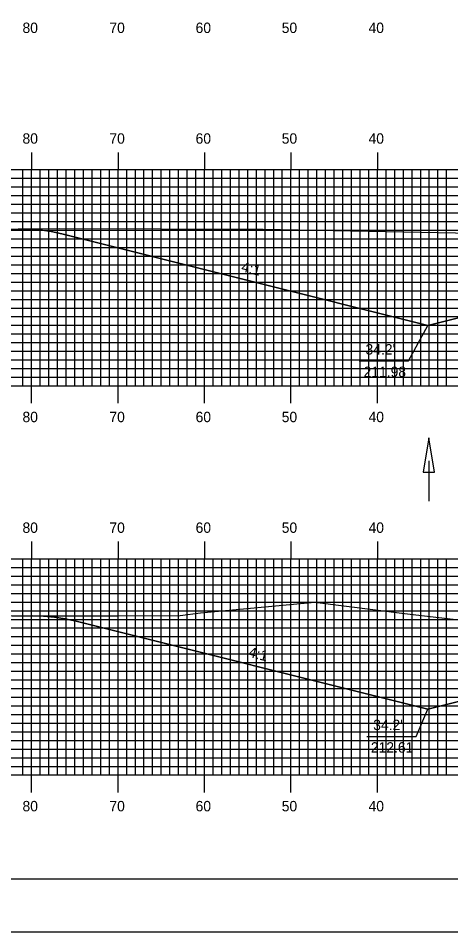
# Model space of a CAD drawing. Extents: x 1820818 to 1821161, y 442591 to 442811.
# Drawn here: x 1820902.2 to 1820952.2, y 442590.5 to 442696.2 of the extents above; entities that cross this region are included whole.
import ezdxf

# ---------------------------------------------------------------- set-up
doc = ezdxf.new("R2010")
doc.units = 0
for name, color, linetype in [('ANNOTATION', 7, 'Continuous'), ('BORDER', 7, 'Continuous'), ('D_Drainage_Ditch_Line', 7, 'Continuous'), ('D_Roadway_Centerline', 7, 'Continuous'), ('D_Roadway_SlopeLines', 7, 'Continuous'), ('H_V ANNOTATION', 7, 'Continuous'), ('MAJOR', 7, 'Continuous'), ('MINOR', 7, 'Continuous'), ('PLOT BOUNDARY', 7, 'Continuous'), ('S_Roadway_Centerline', 7, 'Continuous')]:
    doc.layers.add(name, color=color, linetype=linetype)

msp = doc.modelspace()

# ---------------------------------------------------------------- linework, layer by layer
at = {"layer": 'ANNOTATION'}
for points in [[(1820941.61, 442656.56), (1820947.3, 442656.56), (1820949.54, 442660.65)], [(1820942.5, 442613.13), (1820948.19, 442613.13), (1820949.54, 442616.27)]]:
    msp.add_lwpolyline(points, dxfattribs=at)
at = {"layer": 'BORDER'}
msp.add_lwpolyline([(1820834.12, 442596.67), (1821154.12, 442596.67), (1821154.12, 442806.67), (1820834.12, 442806.67)], close=True, dxfattribs=at)
at = {"layer": 'D_Drainage_Ditch_Line'}
msp.add_line((1820949.66, 442645.01), (1820949.66, 442640.32), dxfattribs=at)
msp.add_lwpolyline([(1820949.01, 442643.7), (1820950.32, 442643.7), (1820949.66, 442647.64)], close=True, dxfattribs=at)
at = {"layer": 'D_Roadway_Centerline'}
for points in [[(1820902.22, 442671.82), (1820903.47, 442671.8), (1820904.72, 442671.69), (1820905.97, 442671.5), (1820907.22, 442671.23), (1820949.54, 442660.65), (1820953.54, 442661.65), (1820963.72, 442664.19), (1820971.72, 442664.51), (1820983.72, 442664.75), (1820995.72, 442664.51), (1821005.72, 442664.11), (1821015.72, 442661.61), (1821019.72, 442660.61), (1821053.37, 442669.03), (1821054.62, 442669.3), (1821055.87, 442669.51), (1821057.12, 442669.64), (1821058.37, 442669.7)], [(1820903.86, 442627.07), (1820905.11, 442627.03), (1820906.36, 442626.91), (1820907.61, 442626.72), (1820908.86, 442626.44), (1820949.54, 442616.27), (1820953.54, 442617.27), (1820963.72, 442619.82), (1820971.72, 442620.14), (1820983.72, 442620.38), (1820995.72, 442620.14), (1821005.72, 442619.74), (1821015.72, 442617.24), (1821019.72, 442616.24), (1821053.46, 442624.67), (1821054.71, 442624.94), (1821055.96, 442625.13), (1821057.21, 442625.24), (1821058.46, 442625.26)]]:
    msp.add_lwpolyline(points, dxfattribs=at)
at = {"layer": 'D_Roadway_SlopeLines'}
for points in [[(1820949.54, 442660.65), (1820907.22, 442671.23), (1820905.97, 442671.5), (1820904.72, 442671.69), (1820903.47, 442671.8), (1820902.22, 442671.82)], [(1820963.72, 442664.19), (1820949.54, 442660.65)], [(1820949.54, 442616.27), (1820908.86, 442626.44), (1820907.61, 442626.72), (1820906.36, 442626.91), (1820905.11, 442627.03), (1820903.86, 442627.07)], [(1820963.72, 442619.82), (1820949.54, 442616.27)]]:
    msp.add_lwpolyline(points, dxfattribs=at)
at = {"layer": 'MAJOR'}
for p, q in [((1820903.72, 442680.67), (1820903.72, 442678.67)), ((1820913.72, 442680.67), (1820913.72, 442678.67)), ((1820923.72, 442680.67), (1820923.72, 442678.67)), ((1820933.72, 442680.67), (1820933.72, 442678.67)), ((1820943.72, 442680.67), (1820943.72, 442678.67)), ((1820843.72, 442678.67), (1821123.72, 442678.67)), ((1820843.72, 442678.67), (1821123.72, 442678.67)), ((1820903.72, 442653.67), (1820903.72, 442678.67)), ((1820913.72, 442653.67), (1820913.72, 442678.67)), ((1820923.72, 442653.67), (1820923.72, 442678.67)), ((1820933.72, 442653.67), (1820933.72, 442678.67)), ((1820943.72, 442653.67), (1820943.72, 442678.67)), ((1820843.72, 442673.67), (1821123.72, 442673.67)), ((1820843.72, 442668.67), (1821123.72, 442668.67)), ((1820843.72, 442663.67), (1821123.72, 442663.67)), ((1820843.72, 442658.67), (1821123.72, 442658.67)), ((1820843.72, 442653.67), (1821123.72, 442653.67)), ((1820843.72, 442653.67), (1821123.72, 442653.67)), ((1820903.72, 442651.66), (1820903.72, 442653.67)), ((1820913.72, 442651.66), (1820913.72, 442653.67)), ((1820923.72, 442651.66), (1820923.72, 442653.67)), ((1820933.72, 442651.66), (1820933.72, 442653.67)), ((1820943.72, 442651.66), (1820943.72, 442653.67)), ((1820903.72, 442635.67), (1820903.72, 442633.67)), ((1820913.72, 442635.67), (1820913.72, 442633.67)), ((1820923.72, 442635.67), (1820923.72, 442633.67)), ((1820933.72, 442635.67), (1820933.72, 442633.67)), ((1820943.72, 442635.67), (1820943.72, 442633.67)), ((1820843.72, 442633.67), (1821123.72, 442633.67)), ((1820843.72, 442633.67), (1821123.72, 442633.67)), ((1820903.72, 442608.67), (1820903.72, 442633.67)), ((1820913.72, 442608.67), (1820913.72, 442633.67)), ((1820923.72, 442608.67), (1820923.72, 442633.67)), ((1820933.72, 442608.67), (1820933.72, 442633.67)), ((1820943.72, 442608.67), (1820943.72, 442633.67)), ((1820843.72, 442628.67), (1821123.72, 442628.67)), ((1820843.72, 442623.67), (1821123.72, 442623.67)), ((1820843.72, 442618.67), (1821123.72, 442618.67)), ((1820843.72, 442613.67), (1821123.72, 442613.67)), ((1820843.72, 442608.67), (1821123.72, 442608.67)), ((1820843.72, 442608.67), (1821123.72, 442608.67)), ((1820903.72, 442606.66), (1820903.72, 442608.67)), ((1820913.72, 442606.66), (1820913.72, 442608.67)), ((1820923.72, 442606.66), (1820923.72, 442608.67)), ((1820933.72, 442606.66), (1820933.72, 442608.67)), ((1820943.72, 442606.66), (1820943.72, 442608.67))]:
    msp.add_line(p, q, dxfattribs=at)
at = {"layer": 'MINOR'}
for p, q in [((1820902.72, 442653.67), (1820902.72, 442678.67)), ((1820904.72, 442653.67), (1820904.72, 442678.67)), ((1820905.72, 442653.67), (1820905.72, 442678.67)), ((1820906.72, 442653.67), (1820906.72, 442678.67)), ((1820907.72, 442653.67), (1820907.72, 442678.67)), ((1820908.72, 442653.67), (1820908.72, 442678.67)), ((1820909.72, 442653.67), (1820909.72, 442678.67)), ((1820910.72, 442653.67), (1820910.72, 442678.67)), ((1820911.72, 442653.67), (1820911.72, 442678.67)), ((1820912.72, 442653.67), (1820912.72, 442678.67)), ((1820914.72, 442653.67), (1820914.72, 442678.67)), ((1820915.72, 442653.67), (1820915.72, 442678.67)), ((1820916.72, 442653.67), (1820916.72, 442678.67)), ((1820917.72, 442653.67), (1820917.72, 442678.67)), ((1820918.72, 442653.67), (1820918.72, 442678.67)), ((1820919.72, 442653.67), (1820919.72, 442678.67)), ((1820920.72, 442653.67), (1820920.72, 442678.67)), ((1820921.72, 442653.67), (1820921.72, 442678.67)), ((1820922.72, 442653.67), (1820922.72, 442678.67)), ((1820924.72, 442653.67), (1820924.72, 442678.67)), ((1820925.72, 442653.67), (1820925.72, 442678.67)), ((1820926.72, 442653.67), (1820926.72, 442678.67)), ((1820927.72, 442653.67), (1820927.72, 442678.67)), ((1820928.72, 442653.67), (1820928.72, 442678.67)), ((1820929.72, 442653.67), (1820929.72, 442678.67)), ((1820930.72, 442653.67), (1820930.72, 442678.67)), ((1820931.72, 442653.67), (1820931.72, 442678.67)), ((1820932.72, 442653.67), (1820932.72, 442678.67)), ((1820934.72, 442653.67), (1820934.72, 442678.67)), ((1820935.72, 442653.67), (1820935.72, 442678.67)), ((1820936.72, 442653.67), (1820936.72, 442678.67)), ((1820937.72, 442653.67), (1820937.72, 442678.67)), ((1820938.72, 442653.67), (1820938.72, 442678.67)), ((1820939.72, 442653.67), (1820939.72, 442678.67)), ((1820940.72, 442653.67), (1820940.72, 442678.67)), ((1820941.72, 442653.67), (1820941.72, 442678.67)), ((1820942.72, 442653.67), (1820942.72, 442678.67)), ((1820944.72, 442653.67), (1820944.72, 442678.67)), ((1820945.72, 442653.67), (1820945.72, 442678.67)), ((1820946.72, 442653.67), (1820946.72, 442678.67)), ((1820947.72, 442653.67), (1820947.72, 442678.67)), ((1820948.72, 442653.67), (1820948.72, 442678.67)), ((1820949.72, 442653.67), (1820949.72, 442678.67)), ((1820950.72, 442653.67), (1820950.72, 442678.67)), ((1820951.72, 442653.67), (1820951.72, 442678.67)), ((1820843.72, 442677.67), (1821123.72, 442677.67)), ((1820843.72, 442676.67), (1821123.72, 442676.67)), ((1820843.72, 442675.67), (1821123.72, 442675.67)), ((1820843.72, 442674.67), (1821123.72, 442674.67)), ((1820843.72, 442672.67), (1821123.72, 442672.67)), ((1820843.72, 442671.67), (1821123.72, 442671.67)), ((1820843.72, 442670.67), (1821123.72, 442670.67)), ((1820843.72, 442669.67), (1821123.72, 442669.67)), ((1820843.72, 442667.67), (1821123.72, 442667.67)), ((1820843.72, 442666.67), (1821123.72, 442666.67)), ((1820843.72, 442665.67), (1821123.72, 442665.67)), ((1820843.72, 442664.67), (1821123.72, 442664.67)), ((1820843.72, 442662.67), (1821123.72, 442662.67)), ((1820843.72, 442661.67), (1821123.72, 442661.67)), ((1820843.72, 442660.67), (1821123.72, 442660.67)), ((1820843.72, 442659.67), (1821123.72, 442659.67)), ((1820843.72, 442657.67), (1821123.72, 442657.67)), ((1820843.72, 442656.67), (1821123.72, 442656.67)), ((1820843.72, 442655.67), (1821123.72, 442655.67)), ((1820843.72, 442654.67), (1821123.72, 442654.67)), ((1820902.72, 442608.67), (1820902.72, 442633.67)), ((1820904.72, 442608.67), (1820904.72, 442633.67)), ((1820905.72, 442608.67), (1820905.72, 442633.67)), ((1820906.72, 442608.67), (1820906.72, 442633.67)), ((1820907.72, 442608.67), (1820907.72, 442633.67)), ((1820908.72, 442608.67), (1820908.72, 442633.67)), ((1820909.72, 442608.67), (1820909.72, 442633.67)), ((1820910.72, 442608.67), (1820910.72, 442633.67)), ((1820911.72, 442608.67), (1820911.72, 442633.67)), ((1820912.72, 442608.67), (1820912.72, 442633.67)), ((1820914.72, 442608.67), (1820914.72, 442633.67)), ((1820915.72, 442608.67), (1820915.72, 442633.67)), ((1820916.72, 442608.67), (1820916.72, 442633.67)), ((1820917.72, 442608.67), (1820917.72, 442633.67)), ((1820918.72, 442608.67), (1820918.72, 442633.67)), ((1820919.72, 442608.67), (1820919.72, 442633.67)), ((1820920.72, 442608.67), (1820920.72, 442633.67)), ((1820921.72, 442608.67), (1820921.72, 442633.67)), ((1820922.72, 442608.67), (1820922.72, 442633.67)), ((1820924.72, 442608.67), (1820924.72, 442633.67)), ((1820925.72, 442608.67), (1820925.72, 442633.67)), ((1820926.72, 442608.67), (1820926.72, 442633.67)), ((1820927.72, 442608.67), (1820927.72, 442633.67)), ((1820928.72, 442608.67), (1820928.72, 442633.67)), ((1820929.72, 442608.67), (1820929.72, 442633.67)), ((1820930.72, 442608.67), (1820930.72, 442633.67)), ((1820931.72, 442608.67), (1820931.72, 442633.67)), ((1820932.72, 442608.67), (1820932.72, 442633.67)), ((1820934.72, 442608.67), (1820934.72, 442633.67)), ((1820935.72, 442608.67), (1820935.72, 442633.67)), ((1820936.72, 442608.67), (1820936.72, 442633.67)), ((1820937.72, 442608.67), (1820937.72, 442633.67)), ((1820938.72, 442608.67), (1820938.72, 442633.67)), ((1820939.72, 442608.67), (1820939.72, 442633.67)), ((1820940.72, 442608.67), (1820940.72, 442633.67)), ((1820941.72, 442608.67), (1820941.72, 442633.67)), ((1820942.72, 442608.67), (1820942.72, 442633.67)), ((1820944.72, 442608.67), (1820944.72, 442633.67)), ((1820945.72, 442608.67), (1820945.72, 442633.67)), ((1820946.72, 442608.67), (1820946.72, 442633.67)), ((1820947.72, 442608.67), (1820947.72, 442633.67)), ((1820948.72, 442608.67), (1820948.72, 442633.67)), ((1820949.72, 442608.67), (1820949.72, 442633.67)), ((1820950.72, 442608.67), (1820950.72, 442633.67)), ((1820951.72, 442608.67), (1820951.72, 442633.67)), ((1820843.72, 442632.67), (1821123.72, 442632.67)), ((1820843.72, 442631.67), (1821123.72, 442631.67)), ((1820843.72, 442630.67), (1821123.72, 442630.67)), ((1820843.72, 442629.67), (1821123.72, 442629.67)), ((1820843.72, 442627.67), (1821123.72, 442627.67)), ((1820843.72, 442626.67), (1821123.72, 442626.67)), ((1820843.72, 442625.67), (1821123.72, 442625.67)), ((1820843.72, 442624.67), (1821123.72, 442624.67)), ((1820843.72, 442622.67), (1821123.72, 442622.67)), ((1820843.72, 442621.67), (1821123.72, 442621.67)), ((1820843.72, 442620.67), (1821123.72, 442620.67)), ((1820843.72, 442619.67), (1821123.72, 442619.67)), ((1820843.72, 442617.67), (1821123.72, 442617.67)), ((1820843.72, 442616.67), (1821123.72, 442616.67)), ((1820843.72, 442615.67), (1821123.72, 442615.67)), ((1820843.72, 442614.67), (1821123.72, 442614.67)), ((1820843.72, 442612.67), (1821123.72, 442612.67)), ((1820843.72, 442611.67), (1821123.72, 442611.67)), ((1820843.72, 442610.67), (1821123.72, 442610.67)), ((1820843.72, 442609.67), (1821123.72, 442609.67))]:
    msp.add_line(p, q, dxfattribs=at)
at = {"layer": 'PLOT BOUNDARY'}
msp.add_lwpolyline([(1820817.93, 442590.55), (1821157.93, 442590.55), (1821157.93, 442810.55), (1820817.93, 442810.55)], close=True, dxfattribs=at)
at = {"layer": 'S_Roadway_Centerline'}
for points in [[(1820843.72, 442672.3), (1820844.11, 442672.29), (1820854.74, 442671.9), (1820864.31, 442671.78), (1820874.39, 442671.67), (1820887.74, 442671.75), (1820897.44, 442671.77), (1820906.98, 442671.88), (1820930.49, 442671.78), (1820956.79, 442671.27), (1820959.09, 442671.32), (1820962.35, 442671.22), (1820975.01, 442671), (1820975.43, 442670.99), (1820991.07, 442670.68), (1820998.78, 442670.49), (1821009.44, 442670.25), (1821021.98, 442670.01)], [(1820843.72, 442627.44), (1820847.28, 442627.37), (1820853.39, 442627.27), (1820866.09, 442627.29), (1820870.53, 442627.29), (1820879.54, 442627.29), (1820888, 442627.19), (1820901.45, 442627.07), (1820906.36, 442627.07), (1820913.64, 442627.08), (1820920.92, 442627.11), (1820923.26, 442627.42), (1820936.46, 442628.65), (1820946.85, 442627.34), (1820954.79, 442626.43), (1820968.88, 442626.11), (1820971.93, 442625.99), (1820973.61, 442625.96), (1820992.48, 442625.84), (1820996.3, 442625.75), (1821006.07, 442625.62), (1821014.13, 442625.62), (1821023.16, 442625.59)]]:
    msp.add_lwpolyline(points, dxfattribs=at)

# ---------------------------------------------------------------- texts
at = {"layer": 'ANNOTATION'}
for p in [(1820927.89, 442666.92), (1820928.71, 442622.34)]:
    msp.add_text('4:1', height=1.2, rotation=345.9638, dxfattribs=at).set_placement(p)
for s, p in [("34.2'", (1820942.34, 442657.29)), ('211.98', (1820942.12, 442654.69)), ("34.2'", (1820943.23, 442613.86)), ('212.61', (1820942.96, 442611.26))]:
    msp.add_text(s, height=1.2, dxfattribs=at).set_placement(p)
at = {"layer": 'H_V ANNOTATION'}
for s, p in [('80', (1820902.67, 442694.47)), ('70', (1820912.72, 442694.47)), ('60', (1820922.69, 442694.47)), ('50', (1820932.65, 442694.47)), ('40', (1820942.69, 442694.47)), ('80', (1820902.67, 442681.67)), ('70', (1820912.72, 442681.67)), ('60', (1820922.69, 442681.67)), ('50', (1820932.65, 442681.67)), ('40', (1820942.69, 442681.67)), ('80', (1820902.67, 442649.47)), ('70', (1820912.72, 442649.47)), ('60', (1820922.69, 442649.47)), ('50', (1820932.65, 442649.47)), ('40', (1820942.69, 442649.47)), ('80', (1820902.67, 442636.67)), ('70', (1820912.72, 442636.67)), ('60', (1820922.69, 442636.67)), ('50', (1820932.65, 442636.67)), ('40', (1820942.69, 442636.67)), ('80', (1820902.67, 442604.47)), ('70', (1820912.72, 442604.47)), ('60', (1820922.69, 442604.47)), ('50', (1820932.65, 442604.47)), ('40', (1820942.69, 442604.47))]:
    msp.add_text(s, height=1.2, dxfattribs=at).set_placement(p)

doc.saveas('drawing.dxf')
